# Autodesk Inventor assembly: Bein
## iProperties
Author: Standard
Created: 2002-11
Part Number: Bein
Document SubType Name: Baugruppe
Designer: Standard
Control State: 0
Master: False
Checked Out: False
PropertySet Name: Design Tracking Control
Shininess: 20.0
Angle Display Precision: 2
Document Length Units: 11269
Document Angle Units: 11283
Document Time Units: 11279
Document Mass Units: 11290
Document Length Units Precision: 3
Document Angle Units Precision: 2
Compacted: False
PropertySet Name: _Private Model Information
Density: 0.0
Volumn: 0.0
Area: 0.0
PropertySet Name: Model Information
